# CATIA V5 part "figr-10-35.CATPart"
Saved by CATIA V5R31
Part number: Part1
Bounding box of the stored display mesh (mm): x -80 to 120, y 0 to 190, z 0 to 170
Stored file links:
  D:\PROJECTS\Project 2021\US EDITION\CATIA V5 6R 2021\Resources\Part Files\c10_catia_v5_6r2021_prt\c10_catia_v5_6r2021_prt\figr-10-35.CATPart
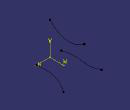
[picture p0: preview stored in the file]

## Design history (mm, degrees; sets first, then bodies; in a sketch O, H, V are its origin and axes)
Set1
  Sketch1 on xy-plane, origin (0, 0, 0), H (1, 0, 0), V (0, 1, 0)
    spline S1 through (-60, 0) (-70, 70) (-70, 170) (-80, 190)
  Sketch2 on yz-plane, origin (0, 0, 0), H (0, 1, 0), V (0, 0, 1)
    spline S1 through (0, 170) (100, 120) (180, 150)
  Sketch3 on xy-plane, origin (0, 0, 0), H (1, 0, 0), V (0, 1, 0)
    spline S1 through (70, 0) (70, 80) (120, 190)
Body1 (main body)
